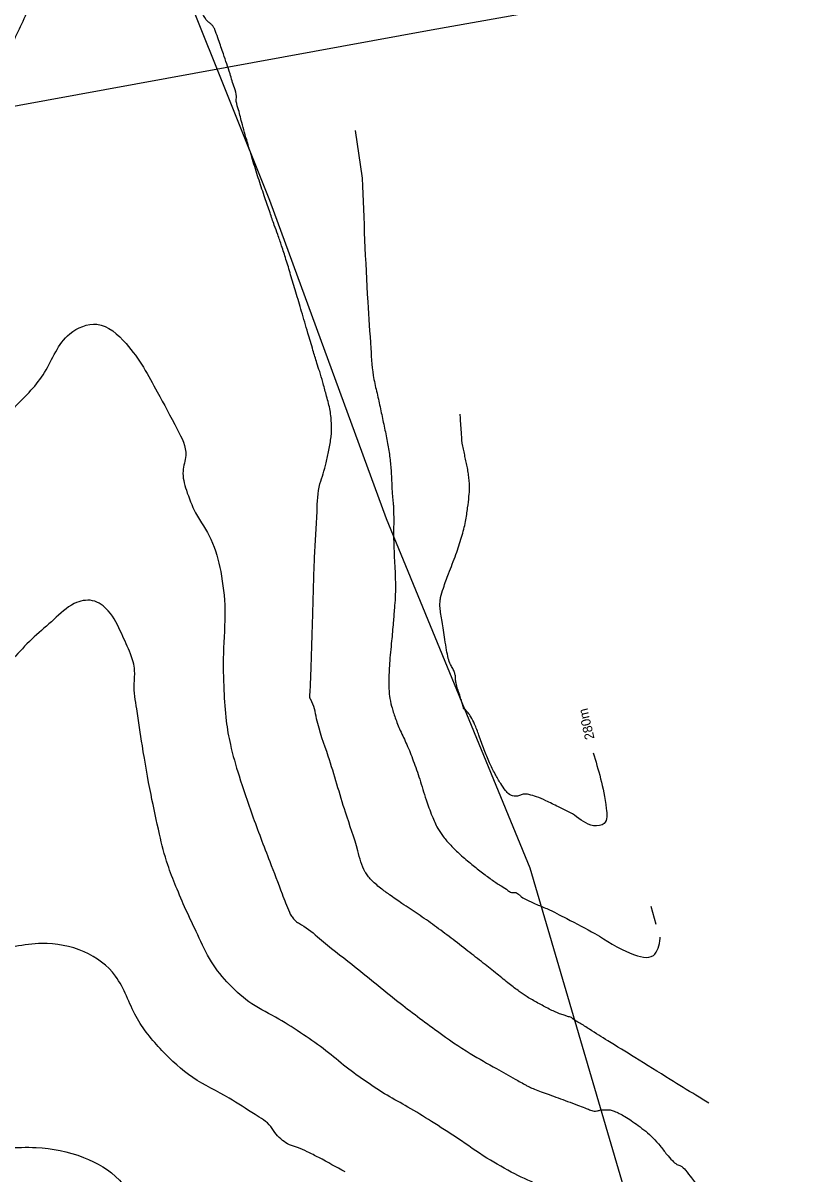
# Model space of a CAD drawing. Extents: x -478495 to -472450, y -1118050 to -1113745.
# Drawn here: x -474853.7 to -474704.8, y -1117290.5 to -1117072.1 of the extents above; entities that cross this region are included whole.
import ezdxf

# ---------------------------------------------------------------- set-up
doc = ezdxf.new("R2010")
doc.units = 0
for name, color, linetype in [('el vedeni_VVN', 7, 'Continuous'), ('hranice kú', 7, 'Continuous'), ('ObPÚ', 7, 'Continuous'), ('Vrstevnice_hlavni', 7, 'Continuous'), ('Vrstevnice_popis', 7, 'Continuous'), ('Vrstevnice_vedlejsi', 7, 'Continuous')]:
    doc.layers.add(name, color=color, linetype=linetype)

msp = doc.modelspace()

# ---------------------------------------------------------------- linework, layer by layer
at = {"layer": 'el vedeni_VVN'}
msp.add_lwpolyline([(-475271.15, -1117163.15), (-475073.59, -1117127.73), (-474776.14, -1117073.38), (-474509.53, -1117026.05)], dxfattribs=at)
at = {"layer": 'hranice kú'}
for p, q in [((-474806.78, -1117105.76), (-474851.29, -1116994.89)), ((-474784.65, -1117166.16), (-474806.78, -1117105.76)), ((-474757.38, -1117232.44), (-474784.65, -1117166.16)), ((-474730.1, -1117325.29), (-474757.38, -1117232.44))]:
    msp.add_line(p, q, dxfattribs=at)
at = {"layer": 'ObPÚ'}
for p, q in [((-474806.78, -1117105.76), (-474851.29, -1116994.89)), ((-474784.65, -1117166.16), (-474806.78, -1117105.76)), ((-474757.38, -1117232.44), (-474784.65, -1117166.16)), ((-474730.1, -1117325.29), (-474757.38, -1117232.44))]:
    msp.add_line(p, q, dxfattribs=at)
at = {"layer": 'Vrstevnice_hlavni'}
for points in [[(-474745.4, -1117210.54), (-474742.9, -1117221.11), (-474743.29, -1117223.96), (-474745.31, -1117224.39), (-474748.96, -1117222.39), (-474751.99, -1117220.8), (-474754.39, -1117219.64), (-474756.17, -1117218.89), (-474757.59, -1117218.48), (-474758.67, -1117218.41), (-474759.4, -1117218.68), (-474760.09, -1117218.78), (-474760.72, -1117218.71), (-474761.3, -1117218.46), (-474762.04, -1117217.69), (-474762.94, -1117216.4), (-474764.01, -1117214.58), (-474765.05, -1117212.44), (-474766.07, -1117209.99), (-474767.07, -1117207.22), (-474767.91, -1117205.12), (-474768.6, -1117203.71), (-474769.14, -1117202.97), (-474769.54, -1117202.48), (-474769.78, -1117202.25), (-474769.88, -1117202.28), (-474769.98, -1117202.13), (-474770.09, -1117201.81), (-474770.21, -1117201.33), (-474770.42, -1117200.6), (-474770.73, -1117199.62), (-474771.12, -1117198.39), (-474771.39, -1117197.37), (-474771.54, -1117196.56), (-474771.56, -1117195.96), (-474771.73, -1117195.3), (-474772.04, -1117194.59), (-474772.49, -1117193.82), (-474772.89, -1117192.64), (-474773.24, -1117191.05), (-474773.53, -1117189.06), (-474773.8, -1117187.26), (-474774.07, -1117185.66), (-474774.32, -1117184.26), (-474774.46, -1117183.02), (-474774.47, -1117181.97), (-474774.37, -1117181.1), (-474773.83, -1117179.3), (-474772.85, -1117176.57), (-474771.44, -1117172.91), (-474770.37, -1117169.61), (-474769.62, -1117166.65), (-474769.22, -1117164.05), (-474768.97, -1117161.92), (-474768.87, -1117160.25), (-474768.92, -1117159.06), (-474769.04, -1117157.91), (-474769.21, -1117156.78), (-474769.43, -1117155.69), (-474769.67, -1117154.58), (-474769.91, -1117153.47), (-474770.16, -1117152.35), (-474770.39, -1117150.13), (-474770.6, -1117146.81), (-474770.63, -1117146.29)], [(-474792.49, -1117290.1), (-474797.5, -1117287.36), (-474799.67, -1117286.27), (-474801.52, -1117285.47), (-474803.05, -1117284.94), (-474804.4, -1117284.1), (-474805.6, -1117282.94), (-474806.62, -1117281.47), (-474809.6, -1117279.19), (-474814.52, -1117276.09), (-474821.4, -1117272.18), (-474827.28, -1117267.02), (-474832.18, -1117260.6), (-474836.09, -1117252.93), (-474842.06, -1117248.31), (-474850.09, -1117246.75), (-474860.18, -1117248.24), (-474867.98, -1117249.27), (-474873.51, -1117249.84), (-474876.76, -1117249.95), (-474880.16, -1117250.15), (-474883.73, -1117250.43), (-474887.45, -1117250.81), (-474893.14, -1117252.09), (-474900.79, -1117254.3), (-474910.39, -1117257.42), (-474918.49, -1117259.97), (-474925.09, -1117261.94), (-474930.17, -1117263.34), (-474936.31, -1117265.91), (-474943.51, -1117269.64), (-474951.75, -1117274.53), (-474957.76, -1117277.86), (-474961.52, -1117279.62), (-474963.03, -1117279.81), (-474967.98, -1117280.54), (-474976.37, -1117281.8), (-474988.2, -1117283.6), (-474996.64, -1117284.74), (-475001.72, -1117285.22), (-475003.41, -1117285.04), (-475005.17, -1117285.08), (-475007, -1117285.33), (-475010.77, -1117286.28)]]:
    msp.add_spline(points, degree=3, dxfattribs=at)
at = {"layer": 'Vrstevnice_vedlejsi'}
for p, q in [((-474790.57, -1117092.45), (-474789.23, -1117101.54)), ((-474733.4, -1117243.11), (-474734.39, -1117239.72))]:
    msp.add_line(p, q, dxfattribs=at)
for points in [[(-474818.06, -1117072.18), (-474818.58, -1117071.79), (-474819.57, -1117070.22), (-474821.05, -1117067.47), (-474823, -1117063.55), (-474824.78, -1117060.09), (-474826.38, -1117057.09), (-474827.81, -1117054.55), (-474829.58, -1117052.83), (-474831.69, -1117051.93), (-474834.15, -1117051.85), (-474836.61, -1117051.87), (-474839.09, -1117051.98), (-474841.58, -1117052.18), (-474844.77, -1117055.39), (-474848.66, -1117061.59), (-474853.24, -1117070.79), (-474856.97, -1117078.73), (-474859.82, -1117085.41), (-474861.8, -1117090.81), (-474864.65, -1117097.06), (-474868.36, -1117104.15), (-474872.93, -1117112.07), (-474876.09, -1117117.52), (-474877.83, -1117120.5), (-474878.16, -1117121.01), (-474878.55, -1117121.45), (-474878.99, -1117121.84), (-474879.5, -1117122.17), (-474884.28, -1117126.15), (-474893.33, -1117133.78), (-474906.67, -1117145.06), (-474915.73, -1117152.81), (-474920.51, -1117157.02), (-474921.01, -1117157.69), (-474921.59, -1117158.31), (-474922.23, -1117158.9), (-474922.95, -1117159.45), (-474925.32, -1117161.96), (-474929.34, -1117166.43), (-474935.03, -1117172.86), (-474940.96, -1117178.62), (-474947.14, -1117183.72), (-474953.57, -1117188.15), (-474958.44, -1117191.36), (-474961.75, -1117193.34), (-474963.5, -1117194.09), (-474966.25, -1117195.17), (-474970.01, -1117196.56), (-474974.78, -1117198.28), (-474980.23, -1117200.05), (-474986.37, -1117201.87), (-474993.18, -1117203.75), (-474998.67, -1117205.25), (-475002.81, -1117206.37), (-475005.62, -1117207.11), (-475011.03, -1117208.89), (-475019.04, -1117211.71), (-475029.65, -1117215.55), (-475038.15, -1117218.82), (-475044.54, -1117221.5), (-475048.82, -1117223.59), (-475054.6, -1117224.94), (-475061.88, -1117225.54), (-475070.66, -1117225.39), (-475079.9, -1117225.8), (-475089.6, -1117226.79), (-475099.76, -1117228.36), (-475107.65, -1117229.42), (-475113.28, -1117229.97), (-475116.64, -1117230.02), (-475121.91, -1117229.51), (-475129.08, -1117228.42), (-475138.16, -1117226.77), (-475145.74, -1117225.79), (-475151.82, -1117225.48), (-475156.4, -1117225.84), (-475163.19, -1117227.05), (-475172.18, -1117229.1), (-475183.38, -1117232.01), (-475191.47, -1117234.18), (-475196.43, -1117235.62), (-475198.27, -1117236.32), (-475199.71, -1117236.9), (-475200.73, -1117237.35), (-475201.35, -1117237.69), (-475201.94, -1117238.14), (-475202.49, -1117238.69), (-475203.02, -1117239.34), (-475204.01, -1117240.81), (-475205.47, -1117243.1), (-475207.39, -1117246.2), (-475210.55, -1117251.73), (-475214.97, -1117259.68), (-475220.62, -1117270.05), (-475225.92, -1117278.61), (-475230.86, -1117285.34)], [(-474723.44, -1117277.01), (-474725.88, -1117275.54), (-474730.75, -1117272.54), (-474737.48, -1117268.37), (-474742.59, -1117265.2), (-474746.08, -1117263.02), (-474747.95, -1117261.84), (-474749.22, -1117261.06), (-474749.88, -1117260.67), (-474749.93, -1117260.67), (-474750.26, -1117260.57), (-474750.88, -1117260.37), (-474751.78, -1117260.06), (-474752.74, -1117259.66), (-474753.75, -1117259.18), (-474754.82, -1117258.61), (-474755.87, -1117258.04), (-474756.92, -1117257.46), (-474757.95, -1117256.87), (-474759.42, -1117255.85), (-474761.31, -1117254.41), (-474763.63, -1117252.54), (-474766.25, -1117250.46), (-474769.16, -1117248.18), (-474772.37, -1117245.7), (-474775.52, -1117243.36), (-474778.63, -1117241.18), (-474781.69, -1117239.14), (-474784.06, -1117237.5), (-474785.75, -1117236.26), (-474786.74, -1117235.42), (-474787.56, -1117234.63), (-474788.2, -1117233.88), (-474788.67, -1117233.18), (-474790.07, -1117229.17), (-474792.41, -1117221.85), (-474795.69, -1117211.22), (-474797.9, -1117204.09), (-474799.03, -1117200.45), (-474799.1, -1117200.32), (-474799.14, -1117200.2), (-474799.18, -1117200.09), (-474799.2, -1117199.99), (-474799.2, -1117199.85), (-474799.2, -1117199.68), (-474799.18, -1117199.46), (-474799.15, -1117199.15), (-474799.12, -1117198.74), (-474799.09, -1117198.24), (-474798.93, -1117193.86), (-474798.66, -1117185.6), (-474798.28, -1117173.48), (-474797.81, -1117164.77), (-474797.27, -1117159.49), (-474796.66, -1117157.62), (-474796.1, -1117155.51), (-474795.6, -1117153.16), (-474795.16, -1117150.57), (-474795.09, -1117147.94), (-474795.41, -1117145.27), (-474796.1, -1117142.56), (-474796.73, -1117140.22), (-474797.32, -1117138.23), (-474797.84, -1117136.6), (-474798.59, -1117134.16), (-474799.56, -1117130.9), (-474800.75, -1117126.82), (-474801.84, -1117123.13), (-474802.83, -1117119.83), (-474803.72, -1117116.92), (-474804.54, -1117114.38), (-474805.28, -1117112.21), (-474805.94, -1117110.41), (-474806.75, -1117108.09), (-474807.72, -1117105.26), (-474808.83, -1117101.92), (-474809.93, -1117098.42), (-474811.03, -1117094.75), (-474812.12, -1117090.93), (-474812.83, -1117088.19), (-474813.17, -1117086.55), (-474813.12, -1117086), (-474813.52, -1117084.38), (-474814.34, -1117081.7), (-474815.61, -1117077.95), (-474816.53, -1117075.27), (-474817.1, -1117073.66), (-474817.32, -1117073.11), (-474817.64, -1117072.62), (-474818.06, -1117072.18)], [(-474789.23, -1117101.54), (-474788.19, -1117125.01), (-474787.62, -1117133.82), (-474787.01, -1117139.72), (-474786.34, -1117142.7), (-474785.7, -1117145.65), (-474785.08, -1117148.58), (-474784.48, -1117151.49), (-474784.04, -1117154.27), (-474783.76, -1117156.94), (-474783.64, -1117159.48), (-474783.53, -1117161.44), (-474783.42, -1117162.83), (-474783.33, -1117163.64), (-474783.28, -1117164.9), (-474783.26, -1117166.61), (-474783.29, -1117168.76), (-474783.25, -1117171.1), (-474783.15, -1117173.64), (-474783, -1117176.37), (-474782.94, -1117178.85), (-474782.98, -1117181.09), (-474783.13, -1117183.09), (-474783.35, -1117185.84), (-474783.67, -1117189.34), (-474784.06, -1117193.6), (-474784.19, -1117197.09), (-474784.06, -1117199.79), (-474783.66, -1117201.73), (-474782.98, -1117203.91), (-474782.02, -1117206.32), (-474780.78, -1117208.99), (-474779.54, -1117212.06), (-474778.33, -1117215.55), (-474777.12, -1117219.45), (-474775.98, -1117222.56), (-474774.89, -1117224.9), (-474773.86, -1117226.45), (-474772.44, -1117228.11), (-474770.63, -1117229.86), (-474768.43, -1117231.73), (-474766.38, -1117233.35), (-474764.49, -1117234.74), (-474762.76, -1117235.89), (-474761.56, -1117236.66), (-474760.9, -1117237.05), (-474760.76, -1117237.06), (-474760.58, -1117237.07), (-474760.36, -1117237.08), (-474760.1, -1117237.09), (-474759.78, -1117237.23), (-474759.42, -1117237.49), (-474758.99, -1117237.89), (-474757.98, -1117238.47), (-474756.38, -1117239.21), (-474754.19, -1117240.13), (-474750.41, -1117242.02), (-474745.04, -1117244.87), (-474738.07, -1117248.69), (-474733.96, -1117249), (-474732.69, -1117245.81), (-474732.68, -1117245.54)], [(-474868.94, -1117155.22), (-474861.63, -1117150.45), (-474855.17, -1117144.83), (-474849.55, -1117138.37), (-474844.78, -1117131.06), (-474839.62, -1117129.25), (-474834.08, -1117132.92), (-474828.15, -1117142.08), (-474824.37, -1117149.16), (-474822.75, -1117154.16), (-474823.27, -1117157.08), (-474822.64, -1117160.7), (-474820.88, -1117165.02), (-474817.97, -1117170.04), (-474816.12, -1117176.16), (-474815.33, -1117183.38), (-474815.6, -1117191.69), (-474815.51, -1117198.73), (-474815.07, -1117204.49), (-474814.28, -1117208.99), (-474812.63, -1117214.93), (-474810.14, -1117222.32), (-474806.81, -1117231.16), (-474804.45, -1117237.31), (-474803.08, -1117240.77), (-474802.69, -1117241.53), (-474802.17, -1117242.19), (-474801.53, -1117242.73), (-474800.77, -1117243.17), (-474797.33, -1117245.81), (-474791.23, -1117250.67), (-474782.47, -1117257.73), (-474774.96, -1117263.38), (-474768.72, -1117267.63), (-474763.73, -1117270.47), (-474760.2, -1117272.47), (-474758.11, -1117273.64), (-474757.49, -1117273.97), (-474756.54, -1117274.38), (-474755.29, -1117274.86), (-474753.73, -1117275.42), (-474752.05, -1117276.03), (-474750.26, -1117276.7), (-474748.36, -1117277.42), (-474746.96, -1117277.95), (-474746.07, -1117278.3), (-474745.67, -1117278.46), (-474745.21, -1117278.53), (-474744.69, -1117278.5), (-474744.1, -1117278.37), (-474743.49, -1117278.3), (-474742.84, -1117278.29), (-474742.17, -1117278.33), (-474741.37, -1117278.56), (-474740.43, -1117278.98), (-474739.35, -1117279.59), (-474738.16, -1117280.35), (-474736.84, -1117281.28), (-474735.41, -1117282.38), (-474734.02, -1117283.65), (-474732.69, -1117285.11), (-474731.42, -1117286.76), (-474730.34, -1117287.94), (-474729.47, -1117288.65), (-474728.79, -1117288.91), (-474727.86, -1117289.77), (-474726.69, -1117291.23), (-474725.27, -1117293.3), (-474724.01, -1117294.97), (-474722.92, -1117296.26), (-474722, -1117297.16), (-474720.9, -1117298.67), (-474719.63, -1117300.77), (-474718.19, -1117303.48), (-474717, -1117305.83), (-474716.06, -1117307.82), (-474714.7, -1117311.09)], [(-474709.1, -1117343.92), (-474711.9, -1117337.2), (-474713.83, -1117333.1), (-474716.27, -1117328.27), (-474719.24, -1117322.7), (-474721.47, -1117318.74), (-474722.97, -1117316.39), (-474723.75, -1117315.64), (-474724.5, -1117314.78), (-474725.24, -1117313.81), (-474725.96, -1117312.74), (-474726.75, -1117311.8), (-474727.6, -1117311.01), (-474728.51, -1117310.36), (-474729.14, -1117309.78), (-474729.48, -1117309.28), (-474729.54, -1117308.85), (-474729.77, -1117308.37), (-474730.18, -1117307.84), (-474730.78, -1117307.25), (-474731.5, -1117306.38), (-474732.34, -1117305.23), (-474733.29, -1117303.8), (-474734.2, -1117302.45), (-474735.06, -1117301.19), (-474735.87, -1117300.01), (-474736.63, -1117299.14), (-474737.35, -1117298.58), (-474738.03, -1117298.33), (-474738.57, -1117298.22), (-474738.98, -1117298.26), (-474739.26, -1117298.45), (-474739.63, -1117298.47), (-474740.09, -1117298.33), (-474740.64, -1117298.03), (-474741.53, -1117297.61), (-474742.75, -1117297.06), (-474744.31, -1117296.4), (-474746.92, -1117295.45), (-474750.58, -1117294.22), (-474755.29, -1117292.7), (-474760.28, -1117290.45), (-474765.55, -1117287.46), (-474771.1, -1117283.73), (-474776.11, -1117280.5), (-474780.58, -1117277.77), (-474784.5, -1117275.54), (-474788.4, -1117273.01), (-474792.28, -1117270.2), (-474796.14, -1117267.09), (-474800.41, -1117264.05), (-474805.1, -1117261.08), (-474810.19, -1117258.18), (-474814.45, -1117254.55), (-474817.88, -1117250.19), (-474820.48, -1117245.09), (-474822.72, -1117240.33), (-474824.62, -1117235.9), (-474826.17, -1117231.81), (-474827.74, -1117226), (-474829.35, -1117218.47), (-474830.99, -1117209.24), (-474832.05, -1117202.23), (-474832.54, -1117197.46), (-474832.46, -1117194.92), (-474833.26, -1117191.77), (-474834.92, -1117187.99), (-474837.46, -1117183.61), (-474840.46, -1117181.69), (-474843.91, -1117182.24), (-474847.81, -1117185.26), (-474851.54, -1117188.57), (-474855.07, -1117192.19), (-474858.42, -1117196.09), (-474861.35, -1117200.03), (-474863.86, -1117203.99), (-474865.95, -1117207.98), (-474868.67, -1117210.82), (-474872.02, -1117212.53), (-474876.01, -1117213.1), (-474881.51, -1117214.8), (-474888.51, -1117217.62), (-474897.02, -1117221.57), (-474904.3, -1117225.06), (-474910.35, -1117228.09), (-474915.17, -1117230.65), (-474918.86, -1117232.65), (-474921.39, -1117234.08), (-474922.78, -1117234.95), (-474925.44, -1117236), (-474929.36, -1117237.22), (-474934.55, -1117238.61), (-474939.78, -1117240.02), (-474945.04, -1117241.46), (-474950.33, -1117242.91), (-474954.35, -1117244.17), (-474957.09, -1117245.24)], [(-475069.44, -1117316.65), (-475059.16, -1117317.88), (-475051.36, -1117318.79), (-475046.04, -1117319.39), (-475043.2, -1117319.68), (-475037.23, -1117320.21), (-475028.13, -1117320.99), (-475015.91, -1117322.03), (-475007.37, -1117322.68), (-475002.51, -1117322.96), (-475001.34, -1117322.86), (-474999.12, -1117322.46), (-474995.88, -1117321.76), (-474991.59, -1117320.76), (-474985.7, -1117319.11), (-474978.2, -1117316.81), (-474969.1, -1117313.87), (-474960.06, -1117311.44), (-474951.07, -1117309.53), (-474942.13, -1117308.12), (-474934.72, -1117305.73), (-474928.81, -1117302.36), (-474924.42, -1117298), (-474918.03, -1117294.56), (-474909.63, -1117292.02), (-474899.22, -1117290.38), (-474891.31, -1117289.03), (-474885.88, -1117287.97), (-474882.94, -1117287.18), (-474880.24, -1117286.68), (-474877.79, -1117286.44), (-474875.57, -1117286.49), (-474870.4, -1117286.34), (-474862.26, -1117285.99), (-474851.15, -1117285.45), (-474842.18, -1117287.33), (-474835.35, -1117291.63), (-474830.66, -1117298.35), (-474824.65, -1117303.83), (-474817.31, -1117308.07), (-474808.66, -1117311.07), (-474801.73, -1117313.71), (-474796.52, -1117315.98), (-474793.04, -1117317.88), (-474788.93, -1117319.87), (-474784.19, -1117321.94), (-474778.83, -1117324.1), (-474774.74, -1117325.99), (-474771.93, -1117327.61), (-474770.4, -1117328.96), (-474768.45, -1117330.33), (-474766.08, -1117331.71), (-474763.3, -1117333.1), (-474761.23, -1117334.25), (-474759.86, -1117335.15), (-474759.2, -1117335.81), (-474758.53, -1117336.42), (-474757.85, -1117336.96), (-474757.15, -1117337.45), (-474757.06, -1117337.88), (-474757.56, -1117338.26), (-474758.67, -1117338.6), (-474759.63, -1117338.51), (-474760.44, -1117337.99), (-474761.1, -1117337.05), (-474762.34, -1117336.26), (-474764.17, -1117335.61), (-474766.58, -1117335.12), (-474768.48, -1117334.91), (-474769.85, -1117335), (-474770.71, -1117335.37), (-474771.09, -1117336.88), (-474770.99, -1117339.52), (-474770.41, -1117343.29), (-474769.92, -1117346.07), (-474769.51, -1117347.86), (-474769.19, -1117348.65), (-474769.02, -1117349.3), (-474768.99, -1117349.82), (-474769.11, -1117350.22), (-474769.32, -1117351.16), (-474769.61, -1117352.65), (-474769.99, -1117354.7), (-474770.5, -1117356.48), (-474771.16, -1117358), (-474771.94, -1117359.26), (-474775.28, -1117360.33), (-474781.16, -1117361.23), (-474789.6, -1117361.95), (-474796.31, -1117362.67), (-474801.29, -1117363.41), (-474804.55, -1117364.16), (-474807.26, -1117364.7), (-474809.44, -1117365.04), (-474811.07, -1117365.17), (-474813.36, -1117365.8), (-474816.29, -1117366.96)]]:
    msp.add_spline(points, degree=3, dxfattribs=at)

# ---------------------------------------------------------------- texts
at = {"layer": 'Vrstevnice_popis'}
msp.add_text(' 280m ', height=1.8, rotation=103.3003, dxfattribs=at).set_placement((-474744.96, -1117208.49))

doc.saveas('drawing.dxf')
